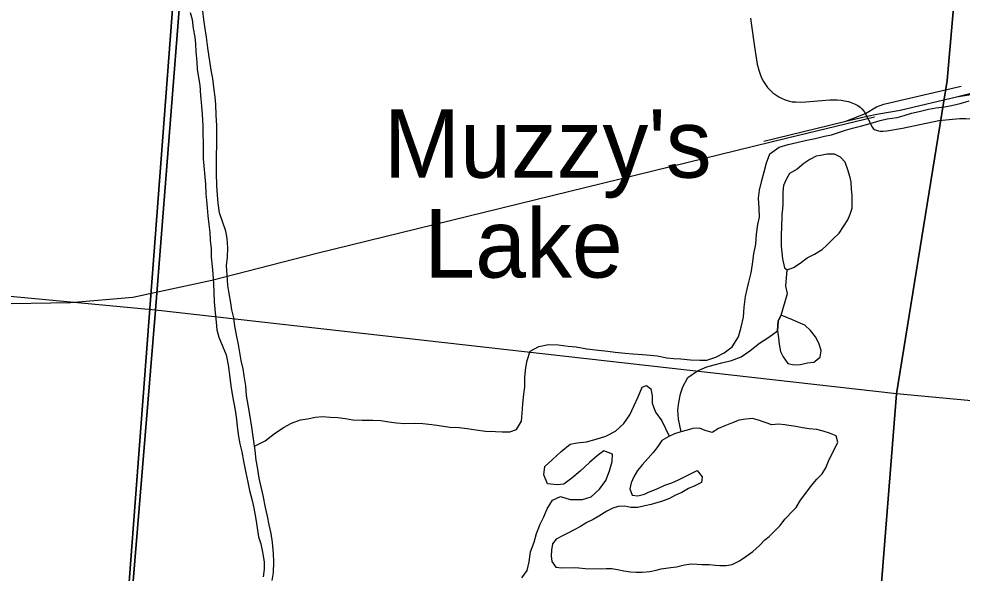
# Model space of a CAD drawing. Extents: x 0 to 1067, y 0 to 440.
# Drawn here: x 799.345 to 800.649, y 351.344 to 352.111 of the extents above; entities that cross this region are included whole.
import ezdxf

# ---------------------------------------------------------------- set-up
doc = ezdxf.new("R2010")
doc.units = 0
for name, color, linetype in [('GM_X_City_Street', 7, 'Continuous'), ('GM_X_Major_River', 7, 'Continuous'), ('GM_X_Minor_Lake', 7, 'Continuous'), ('GM_X_Minor_Lake_Text', 7, 'Continuous'), ('GM_X_Minor_River', 7, 'Continuous'), ('GM_X_Rail_Line', 7, 'Continuous'), ('GM_X_Section', 7, 'Continuous'), ('GM_X_Township_Road', 7, 'Continuous'), ('GM_X_US_Shield', 7, 'Continuous')]:
    doc.layers.add(name, color=color, linetype=linetype)

msp = doc.modelspace()

# ---------------------------------------------------------------- linework, layer by layer
at = {"layer": 'GM_X_City_Street'}
for points in [[(800.3568, 352.1119), (800.3575, 352.1051), (800.3619, 352.0724), (800.366, 352.0486), (800.368, 352.04), (800.3698, 352.0347), (800.372, 352.0294), (800.3746, 352.0244), (800.3773, 352.0201), (800.3803, 352.0161), (800.3837, 352.0123), (800.3875, 352.0089), (800.3915, 352.0058), (800.3957, 352.0031), (800.4002, 352.0008), (800.4047, 351.9989), (800.4106, 351.9972), (800.4144, 351.9965), (800.4194, 351.9961), (800.4257, 351.996), (800.4331, 351.9964), (800.4665, 351.9989), (800.4764, 351.9989), (800.4819, 351.9985), (800.4867, 351.9978), (800.4921, 351.9966), (800.4967, 351.9951), (800.5012, 351.9932), (800.5049, 351.9911), (800.5081, 351.989), (800.5106, 351.9867), (800.5138, 351.983)], [(800.5138, 351.983), (800.5251, 351.9609), (800.5264, 351.9594), (800.528, 351.9581), (800.5304, 351.957), (800.5336, 351.9561), (800.5361, 351.9557), (800.5399, 351.9556), (800.545, 351.956), (800.5669, 351.9598), (800.6169, 351.9703), (800.6268, 351.9716), (800.636, 351.9725), (800.6459, 351.9731), (800.6546, 351.9732), (800.6638, 351.9729), (800.6787, 351.972), (800.8572, 351.9532)]]:
    msp.add_lwpolyline(points, dxfattribs=at)
at = {"layer": 'GM_X_Major_River'}
for points in [[(799.5814, 352.12), (799.5842, 352.11), (799.5859, 352.0978), (799.588, 352.0856), (799.5889, 352.0761), (799.5895, 352.0658), (799.5908, 352.0513), (799.5914, 352.0414), (799.5931, 352.03), (799.5948, 352.0193), (799.596, 352.0052), (799.5973, 351.9904), (799.5982, 351.9789), (799.5991, 351.9633), (799.5992, 351.9515), (799.5994, 351.9401), (799.5996, 351.9302), (799.5998, 351.9177), (799.6007, 351.9078), (799.602, 351.8922), (799.6026, 351.8823), (799.6035, 351.8693), (799.6041, 351.8598), (799.605, 351.8495), (799.6059, 351.8385), (799.6073, 351.8266), (799.6086, 351.8156), (799.6091, 351.8049), (799.6105, 351.7931), (799.6106, 351.7817), (799.6119, 351.7687), (799.6129, 351.7585), (799.6138, 351.7448), (799.6143, 351.733), (799.6148, 351.7196), (799.6161, 351.7044), (799.6174, 351.6918), (799.6187, 351.6808), (799.6212, 351.6708), (799.627, 351.6574), (799.6314, 351.6463), (799.6342, 351.6326), (799.6365, 351.615), (799.6378, 351.6036), (799.6403, 351.5891), (799.6437, 351.57), (799.6458, 351.5571), (799.6467, 351.5475), (799.6484, 351.5334), (799.6501, 351.5235), (799.6529, 351.5124), (799.6554, 351.4991), (799.6585, 351.483), (799.6613, 351.4704), (799.6638, 351.4586), (799.6673, 351.4448), (799.6698, 351.4342), (799.6726, 351.4193), (799.6743, 351.4071), (799.6763, 351.3949), (799.6792, 351.3849), (799.6816, 351.3735), (799.6841, 351.3601), (799.6839, 351.3498), (799.6825, 351.3392)], [(799.695, 351.3341), (799.6967, 351.3454), (799.6974, 351.3595), (799.6968, 351.3717), (799.6956, 351.3869), (799.6935, 351.3995), (799.6907, 351.4113), (799.6886, 351.4232), (799.6858, 351.4354), (799.6827, 351.4518), (799.6799, 351.464), (799.677, 351.4759), (799.6746, 351.4911), (799.6729, 351.5007), (799.6716, 351.514), (799.6703, 351.5239), (799.6682, 351.5369), (799.6669, 351.5464), (799.6645, 351.5609), (799.6625, 351.5746), (799.6597, 351.5903), (799.6584, 351.6036), (799.6564, 351.6173), (799.655, 351.6269), (799.6522, 351.6387), (799.6501, 351.6498), (799.6484, 351.6605), (799.6463, 351.6719), (799.6435, 351.686), (799.6418, 351.6975), (799.6394, 351.7086), (799.6377, 351.7185), (799.6356, 351.7311), (799.6339, 351.7425), (799.6326, 351.757), (799.6321, 351.7695), (799.6331, 351.7817), (799.6337, 351.7946), (799.6328, 351.8072), (799.6311, 351.8175), (799.6224, 351.8427), (799.6204, 351.8561), (799.6194, 351.8679), (799.6185, 351.8801), (799.6181, 351.8983), (799.6179, 351.9082), (799.6187, 351.9504), (799.6185, 351.963), (799.6176, 351.9782), (799.6171, 351.9927), (799.6162, 352.0026), (799.6148, 352.0129), (799.6128, 352.0285), (799.6108, 352.0403), (799.606, 352.0709), (799.6044, 352.0857), (799.602, 352.1006), (799.6006, 352.1101), (799.5993, 352.1223)]]:
    msp.add_lwpolyline(points, dxfattribs=at)
at = {"layer": 'GM_X_Minor_Lake'}
for points in [[(800.4756, 351.9225), (800.4727, 351.9239), (800.4624, 351.924), (800.4533, 351.9219), (800.4476, 351.9212), (800.4388, 351.9167), (800.4304, 351.9111), (800.4212, 351.9033), (800.4104, 351.8974), (800.4058, 351.8887), (800.4022, 351.8808), (800.4014, 351.872), (800.4011, 351.8542), (800.4007, 351.8485), (800.3998, 351.8405), (800.3995, 351.8208), (800.3991, 351.8147), (800.3989, 351.8052), (800.3992, 351.7969), (800.3998, 351.7878), (800.4008, 351.7794), (800.4036, 351.7668), (800.4075, 351.7641)], [(800.4075, 351.7641), (800.4162, 351.767), (800.4254, 351.773), (800.435, 351.7805), (800.445, 351.7856), (800.4557, 351.792), (800.4618, 351.7976), (800.4703, 351.8062), (800.4792, 351.8148), (800.4854, 351.8238), (800.4912, 351.8333), (800.4943, 351.8408), (800.4971, 351.8491), (800.4973, 351.867), (800.4963, 351.8757), (800.4957, 351.8852), (800.4943, 351.8917), (800.4914, 351.9024), (800.4877, 351.9127), (800.481, 351.92), (800.4756, 351.9225)], [(800.3938, 351.6796), (800.3952, 351.6697), (800.3962, 351.661), (800.3979, 351.6511), (800.4016, 351.6434), (800.408, 351.6346), (800.417, 351.6326), (800.4258, 351.6332), (800.4353, 351.6354), (800.4444, 351.6364), (800.4529, 351.6431), (800.4545, 351.6526), (800.4512, 351.6625), (800.4464, 351.6713), (800.4397, 351.6801), (800.4315, 351.6875), (800.4228, 351.691), (800.4145, 351.6949), (800.3992, 351.7014)], [(800.3992, 351.7014), (800.3947, 351.6933), (800.3938, 351.6796)], [(800.4161, 351.4315), (800.4196, 351.4351), (800.4258, 351.4453), (800.4332, 351.455), (800.4409, 351.4656), (800.4483, 351.4746), (800.4559, 351.4817), (800.461, 351.49), (800.4645, 351.4991), (800.4692, 351.5089), (800.4735, 351.5179), (800.4774, 351.5255), (800.4749, 351.5342), (800.4658, 351.5382), (800.4571, 351.5406), (800.4481, 351.5433), (800.4375, 351.5442), (800.4287, 351.5455), (800.4193, 351.5471), (800.4098, 351.5488), (800.4041, 351.5496), (800.3954, 351.5505), (800.3859, 351.5495), (800.3768, 351.5526), (800.3689, 351.5558), (800.3594, 351.5582), (800.3503, 351.5575), (800.3408, 351.5561), (800.3305, 351.5521), (800.3213, 351.548), (800.3122, 351.5444), (800.3034, 351.5388), (800.2939, 351.5416), (800.286, 351.5451), (800.2769, 351.5444), (800.2689, 351.5423), (800.2601, 351.5397), (800.2517, 351.5372), (800.2437, 351.5335), (800.2341, 351.5279), (800.2283, 351.5196), (800.2218, 351.5114), (800.2152, 351.5035), (800.2071, 351.4949), (800.2005, 351.4866), (800.1951, 351.4775), (800.1916, 351.4692), (800.1896, 351.4609), (800.1929, 351.4525), (800.2008, 351.4516), (800.21, 351.4538), (800.2157, 351.4564), (800.2214, 351.4586), (800.2294, 351.4619), (800.2382, 351.4663), (800.2478, 351.4693), (800.2569, 351.4733), (800.2653, 351.4778), (800.2829, 351.4863), (800.2896, 351.4778), (800.2888, 351.4699)], [(800.2888, 351.4699), (800.2796, 351.4654), (800.2708, 351.4614), (800.2616, 351.4562), (800.2528, 351.4521), (800.2444, 351.4477), (800.2337, 351.4436), (800.225, 351.4411), (800.2192, 351.4392), (800.2105, 351.4375), (800.2006, 351.4353), (800.1911, 351.4351), (800.1828, 351.4371), (800.1737, 351.4368), (800.166, 351.4343), (800.158, 351.4302), (800.1469, 351.4231), (800.1389, 351.4187), (800.1301, 351.4146), (800.1213, 351.409), (800.1128, 351.4042), (800.1048, 351.4001), (800.0964, 351.3961), (800.088, 351.3916), (800.0826, 351.3852)], [(800.0826, 351.3852), (800.0813, 351.3761), (800.0808, 351.3682), (800.0819, 351.3606), (800.0875, 351.3529), (800.0954, 351.3516), (800.1129, 351.3522), (800.1193, 351.3517), (800.1281, 351.3508), (800.1485, 351.3506), (800.1569, 351.3508), (800.1649, 351.3507), (800.1728, 351.3495), (800.1815, 351.3475), (800.1906, 351.3462), (800.1986, 351.3457), (800.2069, 351.3456), (800.2172, 351.3466), (800.2263, 351.3488), (800.2332, 351.3502), (800.2427, 351.3516), (800.2541, 351.353), (800.2655, 351.3559), (800.2747, 351.3573), (800.2826, 351.3568), (800.2891, 351.3563), (800.2993, 351.3565), (800.3084, 351.3557), (800.3141, 351.3552), (800.3229, 351.3551), (800.3312, 351.3565), (800.3415, 351.3613), (800.35, 351.3677), (800.3596, 351.3744), (800.3692, 351.3826), (800.3765, 351.3905), (800.3822, 351.395), (800.3903, 351.4028), (800.3976, 351.4103), (800.4042, 351.4193), (800.4161, 351.4315)]]:
    msp.add_lwpolyline(points, dxfattribs=at)
at = {"layer": 'GM_X_Minor_River'}
for points in [[(800.5691, 351.9773), (800.5794, 351.9805), (800.5897, 351.983), (800.6027, 351.9862), (800.6129, 351.9879), (800.6251, 351.9896), (800.6346, 351.9914), (800.6465, 351.9942), (800.659, 351.9978)], [(799.6708, 351.5201), (799.6852, 351.5275), (799.6978, 351.5372), (799.7105, 351.5461), (799.722, 351.552), (799.7342, 351.5563), (799.7438, 351.558), (799.7548, 351.5601), (799.7647, 351.5611), (799.7753, 351.5602), (799.7859, 351.5596), (799.7965, 351.5583), (799.8067, 351.5566), (799.8196, 351.556), (799.8344, 351.5561), (799.8451, 351.5555), (799.8564, 351.5538), (799.867, 351.5525), (799.8784, 351.5516), (799.8936, 351.5517), (799.9034, 351.5515), (799.9159, 351.5502), (799.9258, 351.5485), (799.9406, 351.5463), (799.9538, 351.5457), (799.9648, 351.5444), (799.9769, 351.5427), (799.9902, 351.5409), (800.0038, 351.5403), (800.0133, 351.5401), (800.0236, 351.54), (800.0331, 351.5432), (800.0398, 351.5545), (800.0407, 351.5659), (800.0417, 351.5788), (800.0431, 351.592), (800.0444, 351.6019), (800.0446, 351.6156), (800.046, 351.6288), (800.0477, 351.6387), (800.0517, 351.6515), (800.064, 351.6581), (800.0773, 351.6606), (800.0906, 351.6603), (800.1046, 351.6586), (800.1156, 351.6573), (800.1303, 351.6547), (800.1463, 351.6529), (800.1591, 351.6516), (800.1694, 351.6499), (800.1834, 351.6485), (800.194, 351.6476), (800.2073, 351.647), (800.2183, 351.646), (800.2277, 351.6451), (800.241, 351.6422), (800.2504, 351.6413), (800.2603, 351.6407), (800.2736, 351.6394), (800.2864, 351.6388), (800.2963, 351.639), (800.3085, 351.643), (800.32, 351.6492), (800.3312, 351.6574), (800.3402, 351.6713), (800.3438, 351.6845), (800.3467, 351.6985), (800.3477, 351.7122), (800.3495, 351.727), (800.3519, 351.7372), (800.3544, 351.747), (800.3577, 351.7599), (800.3594, 351.7716), (800.3612, 351.786), (800.3641, 351.7996), (800.3651, 351.8133), (800.3668, 351.8265), (800.3689, 351.8368), (800.3687, 351.8493), (800.3678, 351.863), (800.3692, 351.874), (800.3721, 351.8876), (800.3753, 351.8997), (800.3789, 351.9118), (800.3833, 351.9246), (800.3964, 351.9335), (800.4086, 351.9375), (800.4227, 351.9407), (800.4322, 351.9428), (800.446, 351.9456), (800.4589, 351.9488), (800.4684, 351.9509), (800.4784, 351.9541), (800.4879, 351.957), (800.4978, 351.9599), (800.5089, 351.9627), (800.5219, 351.9663), (800.536, 351.9703), (800.5455, 351.9727), (800.5596, 351.9748), (800.5691, 351.9773)], [(800.2606, 351.5399), (800.2569, 351.5576), (800.256, 351.5705), (800.2573, 351.5804), (800.2597, 351.5925), (800.2629, 351.6023), (800.2699, 351.6152), (800.2833, 351.6241), (800.2963, 351.63), (800.3062, 351.6325), (800.3169, 351.6354), (800.3302, 351.6387), (800.3435, 351.6434), (800.3558, 351.652), (800.3689, 351.6625), (800.3819, 351.671), (800.3938, 351.6796), (800.3947, 351.6933), (800.3992, 351.7014), (800.4078, 351.7314), (800.4056, 351.7413), (800.4075, 351.7641)], [(800.0402, 351.3379), (800.0479, 351.3481), (800.0504, 351.3602), (800.0524, 351.3739), (800.0576, 351.3875), (800.0604, 351.3992), (800.0659, 351.4124), (800.0706, 351.4222), (800.0753, 351.4332), (800.0827, 351.4456), (800.0937, 351.4504), (800.1074, 351.4464), (800.1241, 351.4462), (800.1363, 351.4502), (800.1478, 351.4607), (800.1563, 351.4727), (800.1618, 351.486), (800.1654, 351.4988), (800.1655, 351.5091), (800.1538, 351.5134), (800.1443, 351.5067), (800.1339, 351.4973), (800.1212, 351.4853), (800.1093, 351.4756), (800.0985, 351.4674), (800.089, 351.4664), (800.0758, 351.4681), (800.0706, 351.4803), (800.0723, 351.4921), (800.0827, 351.5018), (800.0946, 351.5127), (800.1073, 351.5227), (800.1168, 351.5249), (800.1297, 351.5262), (800.1431, 351.5299), (800.1564, 351.5339), (800.1698, 351.5409), (800.1813, 351.5514), (800.1895, 351.5634), (800.1953, 351.5755), (800.2012, 351.5883), (800.2067, 351.6016), (800.2128, 351.6041), (800.2188, 351.5995), (800.2206, 351.5896), (800.2208, 351.5797), (800.2252, 351.5671), (800.2341, 351.5549), (800.2442, 351.5337)]]:
    msp.add_lwpolyline(points, dxfattribs=at)
at = {"layer": 'GM_X_Rail_Line'}
for points in [[(800.6415, 352.0032), (800.9919, 352.0898), (801.4135, 352.1927)], [(800.6415, 352.0032), (800.6614, 352.0064), (800.6789, 352.01), (800.8334, 352.048), (800.9987, 352.0885), (801.0218, 352.0922), (801.0428, 352.0953), (801.056, 352.0965), (801.0865, 352.0953), (801.1166, 352.0935)], [(800.4884, 351.9694), (800.5156, 351.98), (800.5307, 351.9892), (800.5409, 351.9932), (800.5508, 351.9955), (800.6478, 352.0181)], [(800.4884, 351.9694), (800.5181, 351.9765), (800.5315, 351.9791), (800.5504, 351.9824), (800.5636, 351.9846), (800.6415, 352.0032)], [(798.0401, 351.838), (798.8679, 351.7573), (799.0475, 351.7429), (799.2616, 351.7247), (799.3341, 351.7173), (799.4163, 351.7188), (799.5025, 351.7262), (799.6118, 351.7496), (799.757, 351.787), (800.4076, 351.9466), (800.5279, 351.9756)], [(800.3752, 351.9421), (800.4827, 351.9681), (800.4884, 351.9694)]]:
    msp.add_lwpolyline(points, dxfattribs=at)
at = {"layer": 'GM_X_Section'}
for points in [[(798.6013, 352.7849), (799.6121, 352.7044), (799.5337, 351.7084), (798.5186, 351.8037)], [(799.6121, 352.7044), (800.6794, 352.6083), (800.6286, 352.0258), (800.5587, 351.5925), (799.5337, 351.7084)], [(800.6794, 352.6083), (801.6612, 352.5101), (801.5595, 351.4988), (800.5587, 351.5925), (800.6286, 352.0258)]]:
    msp.add_lwpolyline(points, close=True, dxfattribs=at)
at = {"layer": 'GM_X_Township_Road'}
for points in [[(798.0401, 353.8616), (798.0401, 350.8021), (799.4572, 350.8021), (799.5626, 352.1981), (799.6113, 352.6978), (799.7017, 353.7093)], [(799.7017, 353.7093), (799.6113, 352.6978), (799.5626, 352.1981), (799.4572, 350.8021), (804.8401, 350.8021)]]:
    msp.add_lwpolyline(points, dxfattribs=at)
at = {"layer": 'GM_X_US_Shield'}
for points in [[(798.4223, 350.8021), (799.4588, 350.8021), (799.5337, 351.7084), (798.5186, 351.8037)], [(799.4588, 350.8021), (800.4958, 350.8021), (800.5587, 351.5925), (799.5337, 351.7084)], [(800.4958, 350.8021), (801.4897, 350.8021), (801.5595, 351.4988), (800.5587, 351.5925)]]:
    msp.add_lwpolyline(points, close=True, dxfattribs=at)

# ---------------------------------------------------------------- texts
at = {"layer": 'GM_X_Minor_Lake_Text'}
for s, rotation, p in [("Muzzy's", 0.0083, (799.8494, 351.8914)), ('Lake', 0.0081, (799.9054, 351.7532))]:
    msp.add_text(s, height=0.0947, rotation=rotation, dxfattribs=at).set_placement(p)

doc.saveas('drawing.dxf')
